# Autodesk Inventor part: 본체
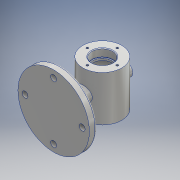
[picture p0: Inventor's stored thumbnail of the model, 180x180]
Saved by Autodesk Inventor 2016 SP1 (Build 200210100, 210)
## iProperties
Created: 2018-12
Part Number: 본체
Material: 알루미늄 6061
Document SubType Name: Modeling
Designer: basic
Mass: 683.222 g
Surface Area: 556.118 cm^2
Volume: 253.045 cm^3
Density: 2.7 g/cm^3
Appearance: 알루미늄 - 평지
Title: 본체
Author: 481208V1013
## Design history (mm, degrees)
sketch "스케치1"
  geometry: C1 r 30 at (0, 0); 1 further point
  constraints: 1 centre point, 1 coincident
  dimensions: "d0" = 60 diameter of C1
extrude "돌출1" new body sketch "스케치1" distance "d1" = 70; taper "d2" = 0 deg
node "작업 평면1"
sketch "스케치2"
  geometry: L1 (30, 70)-(-30, 70) reference; L2 (-30, 0)-(30, 0) reference; L3 (-30, 0)-(30, 0) reference; L4 (30, 70)-(-30, 70) reference; C1 r 55 at (0, 35); 1 further point
  constraints: 1 centre point
  dimensions: "d5" = 110 diameter of C1; "d6" = 35 distance from line of C1.centre L1; "d7" = 46.09772 distance of L1.start C1.centre
extrude "돌출2" join sketch "스케치2" distance "d8" = 10; taper "d9" = 0 deg
sketch "스케치3"
  geometry: L1 (-30, 0)-(30, 0) reference; L2 (0, 0)-(16, 0); L3 (16, 0)-(16, 12); L4 (16, 12)-(14, 12); L5 (30, 70)-(-30, 70) reference; L6 (25, 35)-(25, 15); L7 (25, 15)-(14, 15); L8 (14, 15)-(14, 12); L9 (16, 70)-(16, 58); L10 (14, 55)-(14, 58); L11 (16, 58)-(14, 58); L12 (25, 55)-(14, 55); L13 (25, 35)-(25, 55); L14 (16, 70)-(0, 70); L15 (0, 0)-(0, 70)
  constraints: 26 end point, 3 parallel, 3 perpendicular, 2 vertical, 1 collinear, 1 point on line
  dimensions: "d29" = 12 distance of L2.end L3.end; "d40" = 11 distance of L6.end L7.end; "d41" = 32 diameter of L3 L15; "d42" = 28 diameter of L8 L15; "d43" = 32 diameter of L9 L15; "d44" = 28 diameter of L10 L15; "d45" = 15 distance between parallel lines of L12 L5; "d46" = 55 distance between parallel lines of L7 L5; "d47" = 12 distance between parallel lines of L11 L5; "d48" = 0 distance between parallel lines of L14 L5; "d49" = 35 distance from line of L6.start L5
revolve "회전1" sketch "스케치3" stored, may be unused: angle "d50" = 90 deg
node "작업 평면2"
sketch "스케치4"
  geometry: 1 further point
node "직접 편집1"
sketch "스케치5"
  geometry: L1 (12, -52.478)-(55, -64); L2 (55, -75)-(55, -64) reference; L3 (0, -52.478)-(12, -52.478); L4 (0, -52.478)-(0, -64); L5 (55, -64)-(-55, -64) reference; L6 (0, -64)-(55, -64); 1 further point
  constraints: 8 end point, 1 collinear, 1 horizontal, 1 parallel
  dimensions: "d56" = 75 deg angle of L2 L1; "d57" = 12 distance of L3.start L1.start; "d62" = 11.52182 distance between parallel lines of L5 L3
revolve "회전2" sketch "스케치5" stored, may be unused: angle "d63" = 90 deg
sketch "스케치6"
  geometry: C1 r 12 at (0, 0); 1 further point
  constraints: 1 centre point
  dimensions: "d64" = 24 diameter of C1
extrude "돌출3" join sketch "스케치6" stored distance "d65" = 10; taper "d66" = 0 deg
node "작업 평면3"
sketch "스케치7"
  geometry: L1 (30, 70)-(-30, 70) reference; C1 r 10 at (0, 35); 1 further point
  constraints: 1 centre point
  dimensions: "d68" = 20 diameter of C1; "d69" = 35 distance of point (0, 0) C1.centre; "d70" = 35 distance from line of L1 C1.centre
extrude "돌출4" join sketch "스케치7" stored distance "d71" = 10; taper "d72" = 0 deg
sketch "스케치8"
  geometry: L1 (-10, 37)-(10, 37) reference; 2 further points
  dimensions: "d73" = 23 distance of point (0, 0) point (0, 23); "d74" = 14 distance from line of L1 point (0, 23)
hole "구멍1" sketch "스케치8" at (0, 23) diameter "d75" = 3.242; stored, may be unused: countersink angle "d79" = 90 deg, drill point angle "d81" = 118 deg; dims "d76" = 8, "d77" = 4, "d78" = 2, "d80" = 10
sketch "스케치9"
  geometry: C1 r 10 at (0, 0) reference; 2 further points
  dimensions: "d88" = 44 distance of point (0, 44) C1.centre; "d89" = 79 distance of point (0, -35) point (0, 44)
hole "구멍2" sketch "스케치9" at (0, 44) diameter "d90" = 9; stored, may be unused: countersink angle "d94" = 90 deg, drill point angle "d96" = 0 deg; dims "d91" = 8, "d92" = 4, "d93" = 2, "d95" = 10
sketch "스케치10"
  geometry: C1 r 7 at (0, 0); C2 r 55 at (0, -44) reference; 1 further point
  constraints: 1 centre point
  dimensions: "d97" = 14 diameter of C1; "d98" = 44 distance of C1.centre C2.centre; "d99" = 79 distance of point (0, -79) C1.centre
extrude "돌출5" cut sketch "스케치10" stored distance "d100" = 10; taper "d101" = 0 deg
chamfer "모따기1" distance "d105" = 1; stored, may be unused: second distance "d106" = 2, angle "d107" = 45 deg
sketch "스케치11"
  geometry: C1 r 10 at (0, 0) reference; 1 further point
hole "구멍3" sketch "스케치11" at (0, 0) diameter "d108" = 10; stored, may be unused: countersink angle "d112" = 90 deg, drill point angle "d114" = 0 deg; dims "d109" = 8, "d110" = 4, "d111" = 2, "d113" = 10
chamfer "모따기2" distance "d115" = 1; stored, may be unused: second distance "d116" = 2, angle "d117" = 45 deg
fillet "모깎기1" dims "d118" = 3
fillet "모깎기2" dims "d119" = 3
fillet "모깎기3" dims "d120" = 3
fillet "모깎기4" dims "d121" = 0.3
fillet "모깎기5" dims "d122" = 3
node "작업 평면4"
sketch "스케치12"
  geometry: 2 further points
  constraints: 1 other
feature "엠보싱1" sketch "스케치12" dims "d124" = 0.5, "d125" = 0
node "솔리드1"
pattern_circular "원형 패턴1" dims angle "d83" = 360 deg
mirror "대칭1"
pattern_circular "원형 패턴2" dims angle "d103" = 360 deg
node "투영된 루프1"
feature "이동1" dims "d54" = 1
other parameters: "d3" = -75, "d51" = 35, "d52" = 0, "d53" = 0, "d67" = 37, "d123" = -30.5
